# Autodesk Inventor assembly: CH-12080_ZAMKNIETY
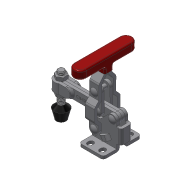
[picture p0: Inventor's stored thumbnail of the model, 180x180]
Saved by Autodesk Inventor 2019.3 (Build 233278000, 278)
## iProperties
Company: Î¢ÈíÖÐ¹ú
Created: 2015-08
Part Number: CH-12080_ZAMKNIETY
Material: Ogólny
Description: STEP AP203
Document SubType Name: Assembly
Designer: CADENGINEERING4
Sending System: SolidWorks 2012
Preprocessor: SwSTEP 2.0
Title: CH-12080.STEP
Author: Î¢ÈíÓÃ»§
Revision Number: ÈÎºÎ
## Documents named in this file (9)
- D:\Vault_2016\Projekty\NASZ KATALOG\CLAMPTEK\STRONA\Vertical toggle clamp\CH-12080\CH-12080_ZAMKNIETY.iam
- D:\Vault_2016\Projekty\NASZ KATALOG\CLAMPTEK\STEP FILES\Vertical toggle clamp\CH-12080\CH-12050-01 FLANGED BASE.ipt
- D:\Vault_2016\Projekty\NASZ KATALOG\CLAMPTEK\STEP FILES\Vertical toggle clamp\CH-12080\CH-12070-03 T-HANDLE.ipt
- D:\Vault_2016\Projekty\NASZ KATALOG\CLAMPTEK\STEP FILES\Vertical toggle clamp\CH-12080\CH-12050-07.ipt
- D:\Vault_2016\Projekty\NASZ KATALOG\CLAMPTEK\STEP FILES\Vertical toggle clamp\CH-12080\CH-12050-06.ipt
- D:\Vault_2016\Projekty\NASZ KATALOG\CLAMPTEK\STEP FILES\Vertical toggle clamp\CH-12080\CH-12050-04 CONNECTING-PLATE.ipt
- D:\Vault_2016\Projekty\NASZ KATALOG\CLAMPTEK\STEP FILES\Vertical toggle clamp\CH-12080\CH-FC-14134 Nut.ipt
- D:\Vault_2016\Projekty\NASZ KATALOG\CLAMPTEK\STEP FILES\Vertical toggle clamp\CH-12080\CH-FC-14134 SPINDLE SUPPLIED.ipt
- D:\Vault_2016\Projekty\NASZ KATALOG\CLAMPTEK\STEP FILES\Vertical toggle clamp\CH-12080\CH-12080-02 SOLID BAR_Ä¬ÈÏ_°´¼Ó¹¤_.ipt
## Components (11 placed, 11 different names)
1. CH-12050-01 FLANGED BASE_1
2. CH-12070-03 T-HANDLE_2
3. CH-12050-07_3
4. CH-12050-07_4
5. CH-12050-06_5
6. CH-12050-04 CONNECTING-PLATE_6
7. CH-12050-06_7
8. CH-FC-14134 Nut_8
9. CH-FC-14134 SPINDLE SUPPLIED_9
10. CH-FC-14134 Nut_10
11. CH-12080-02 SOLID BAR_Ä¬ÈÏ<°´¼Ó¹¤>_11
